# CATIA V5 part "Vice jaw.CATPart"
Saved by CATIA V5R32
Part number: Sliding Jaw
Bounding box of the stored display mesh (mm): x -32 to 32, y -16 to 16, z -9 to 36
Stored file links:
  D:\PROJECTS\Project 2022\CATIA V5 6R 2022\Resources\Tutorial Files\c13_catia_v5_6r2022_tut\c13tut2\Bench vice\Vice jaw.CATPart
  C:\Program Files\Dassault Systemes\B09\intel_a\reffiles\standard\MetricThickPitch.txt
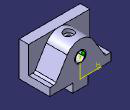
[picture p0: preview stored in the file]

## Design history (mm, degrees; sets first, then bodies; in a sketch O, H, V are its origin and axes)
Body1 (main body)
  Sketch1 on xy-plane, origin (0, 0, 0), H (1, 0, 0), V (0, 1, 0)
    line L1 (-32, -16) -> (32, -16)
    line L2 (32, -16) -> (32, 16)
    line L3 (32, 16) -> (-32, 16)
    line L4 (-32, 16) -> (-32, -16)
    distance H L1 = 16
    distance V L4 = 32
    length L4 = 32
    length L1 = 64
    horizontal: L1 H, L3 H
    vertical: L2 V, L4 V
  Pad1: profile Sketch1, direction (0, 0, 1), length 8
  Sketch2 on face of Pad1, origin (0, -16, 0), H (1, 0, 0), V (0, 0, 1)
    point P1 (-32, 0)
    line L1 (-32, 0) -> (32, 0)
    line L2 (32, 0) -> (32, 36)
    line L3 (32, 36) -> (-32, 36)
    line L4 (-32, 36) -> (-32, 0)
    reference projected line E1 (32, 0) -> (32, 8) from edge of Pad1
    reference projected line E2 (-32, 8) -> (-32, 0) from edge of Pad1
    length L2 = 36
    coincidence: P1 H, L2 E1, L4 E2
    horizontal: L1 H, L3 H
    vertical: L2 V, L4 V
  Pad2: profile Sketch2, direction (0, 1, 0), length 10
  Sketch3 on face of Pad1, origin (0, 16, 0), H (-1, 0, 0), V (0, 0, 1)
    arc A1 centre (0, 20) radius 16 from (13.6777, 28.3018) to (-13.6777, 28.3018) ccw
    point P1 (0, 20)
    reference projected line E1 (-32, 36) -> (32, 36) from edge of Pad2
    line L1 (-26, 8) -> (-13.6777, 28.3018)
    point P2 (-26, 8)
    line L2 (13.6777, 28.3018) -> (26, 8)
    point P3 (26, 8)
    reference projected line E2 (32, 8) -> (-32, 8) from edge of Pad1
    reference projected line E3 (32, 8) -> (-32, 8) from edge of Pad1
    line L3 (-26, 8) -> (26, 8)
    radius A1 = 16
    length L3 = 52
    distance V P3 = 26
    coincidence: P1 V, E2 P2, E3 P3
    tangency: A1 E1, L2 A1, L1 A1
    horizontal: L3 H
  Pad3: profile Sketch3, direction (0, -1, 0), up to the existing solid (limit type 2)
  Fillet1: radius 3, on 2 edges
  Sketch4 on face of Pad1, origin (-2.6964, 16, 22.8197), H (1, 0, 0), V (0, 0, -1)
    point P1 (2.6964, 2.8197)
    reference projected arc E1 centre (2.6964, 2.8197) radius 16 from (-10.9814, -5.4821) to (16.3741, -5.4821) ccw from edge of Pad3
    concentricity: P1 E1
  Hole1: placed by Sketch4, at (0, 16, 20) direction (0, -1, 0), diameter 12, depth 22, V-bottom angle 120
  Sketch5 on face of Pad1, origin (0, 16, 0), H (-1, 0, 0), V (0, 0, 1)
    point P1 (-8, 0)
    line L1 (-8, 0) -> (8, 0)
    line L2 (8, 0) -> (8, -9)
    line L3 (8, -9) -> (-8, -9)
    line L4 (-8, -9) -> (-8, 0)
    distance V L2 = 8
    length L3 = 16
    length L4 = 9
    coincidence: P1 H
    horizontal: L1 H, L3 H
    vertical: L2 V, L4 V
  Pad4: profile Sketch5, direction (0, -1, 0), length 32
  Sketch6 on face of Pad4, origin (-0.598, -1.2346, -9), H (1, 0, 0), V (0, -1, 0)
    point P1 (0.848, -9.2346)
    reference projected line E1 (8.598, -17.2346) -> (-7.402, -17.2346) from edge of Pad4
    reference projected line E2 (8.598, 14.7654) -> (8.598, -17.2346) from edge of Pad4
    distance P1 E1 = 8
    distance P1 E2 = 7.75
  Hole2: placed by Sketch6, at (0.25, 8, -9) direction (0, 0, 1), diameter 5, depth 16, V-bottom angle 120, threaded, thread diameter 6, thread depth 16, pitch 1
  RectPattern1: of Hole2, direction 1 instances 2, spacing 16, along edge of Pad4 reversed
  Sketch7 on face of Pad2, origin (-19.6018, -13.7351, 36), H (1, 0, 0), V (0, 1, 0)
    point P1 (19.6018, 17.7351)
    reference intersected line E1 through (19.6018, 0) direction (0, 1) from yz-plane
    reference projected line E2 (51.6018, -2.2649) -> (-12.3982, -2.2649) from edge of Pad2
    distance P1 E2 = 20
    coincidence: E1 P1
  Hole3: placed by Sketch7, at (0, 4, 36) direction (0, 0, -1), diameter 5, depth 16, V-bottom angle 120, counterbore diameter 10, counterbore depth 4, threaded "M6", thread diameter 6, thread depth 11, pitch 1
  Sketch8 on face of Pad4, origin (0, 16, 0), H (-1, 0, 0), V (0, 0, 1)
    circle A1 centre (0, 20) radius 5.0626
    point P1 (0, 20)
    reference projected circle E1 centre (0, 20) radius 6 from edge [face of Pad3 | face of Hole1]
    coincidence: P1 V
    concentricity: A1 E1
